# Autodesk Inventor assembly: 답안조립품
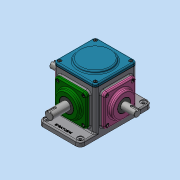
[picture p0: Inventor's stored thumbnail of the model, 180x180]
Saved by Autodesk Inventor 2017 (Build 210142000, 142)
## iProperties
Part Number: 답안조립품
Material: 일반
Document SubType Name: Assembly
Designer: MRC
Author: MRC
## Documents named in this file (16)
- C:\Users\MRC\Desktop\620307V1014\답안조립품.iam
- C:\Users\MRC\Desktop\620307V1014\본체.ipt
- C:\Users\MRC\Desktop\620307V1014\개스킷.ipt
- C:\Users\MRC\Desktop\620307V1014\메인베벨기어.ipt
- C:\Users\MRC\Desktop\620307V1014\메인축.ipt
- C:\Users\MRC\Desktop\620307V1014\메인커버.ipt
- C:\Users\MRC\Desktop\620307V1014\베어링 6203.ipt
- C:\Users\MRC\Desktop\620307V1014\베어링 6204.ipt
- C:\Users\MRC\Desktop\620307V1014\볼트 M4.ipt
- C:\Users\MRC\Desktop\620307V1014\상부커버.ipt
- C:\Users\MRC\Desktop\620307V1014\서브베벨기어.ipt
- C:\Users\MRC\Desktop\620307V1014\서브축.ipt
- C:\Users\MRC\Desktop\620307V1014\서브커버.ipt
- C:\Users\MRC\Desktop\620307V1014\오일 실 17 32 8.ipt
- C:\Users\MRC\Desktop\620307V1014\오일 실 20 35 8.ipt
- C:\Users\MRC\Desktop\620307V1014\키 4x4.ipt
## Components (1 placed, 1 different names)
1. 개스킷:1
